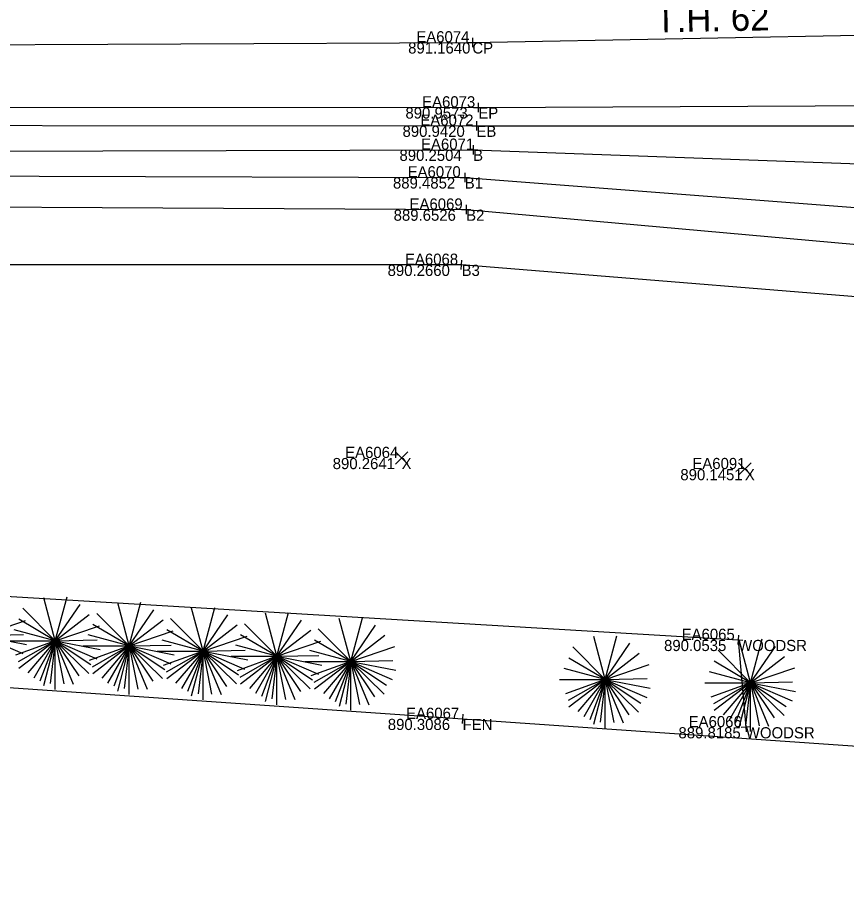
# Model space of a CAD drawing. Extents: x 179044 to 189691, y 286531 to 301257.
# Drawn here: x 180030.9 to 180120, y 300496.5 to 300591.3 of the extents above; entities that cross this region are included whole.
import ezdxf

# ---------------------------------------------------------------- set-up
doc = ezdxf.new("R2010")
doc.units = 0
for name, color, linetype in [('Default', 7, 'Continuous'), ('PV_X_COP', 7, 'Continuous'), ('PV_X_EOP', 7, 'Continuous'), ('PV_X_Shoulder_Aggregate', 7, 'Continuous'), ('RD_X_Fence', 7, 'Continuous'), ('SV_X_Break_Lines', 7, 'Continuous'), ('SV_X_Random_Point', 7, 'Continuous'), ('SV_X_Shot_Marker', 7, 'Continuous'), ('SV_X_Text_Comment', 7, 'Continuous'), ('SV_X_Text_Elevation', 7, 'Continuous'), ('SV_X_Text_Name', 7, 'Continuous'), ('VG_X_Cells', 7, 'Continuous'), ('VG_X_Text', 7, 'Continuous'), ('VG_X_Tree_Line_Lt', 7, 'Continuous')]:
    doc.layers.add(name, color=color, linetype=linetype)

msp = doc.modelspace()

# ---------------------------------------------------------------- linework, layer by layer
at = {"layer": 'PV_X_COP'}
msp.add_lwpolyline([(179370.611, 300584.893), (179476.831, 300585.936), (179562.951, 300586.92), (179659.852, 300587.603), (179771.173, 300587.773), (179881.154, 300588.595), (179985.728, 300588.166), (180079.826, 300588.612), (180147.691, 300589.874), (180172.034, 300590.636), (180187.456, 300591.905), (180203.618, 300593.325)], dxfattribs=at)
at = {"layer": 'PV_X_EOP'}
msp.add_lwpolyline([(179371.146, 300578.051), (179477.168, 300579.528), (179563.012, 300579.455), (179660.626, 300579.907), (179772.349, 300580.843), (179883.302, 300581.216), (179986.953, 300581.659), (180080.461, 300581.624), (180131.142, 300581.875), (180152.421, 300580.897), (180177.372, 300581.245), (180192.481, 300580.813), (180205.116, 300578.916), (180211.895, 300576.366), (180217.061, 300570.924), (180226.256, 300546.032), (180252.64, 300475.662), (180284.891, 300388.784), (180312.046, 300315.753), (180341.998, 300235.308)], dxfattribs=at)
at = {"layer": 'PV_X_Shoulder_Aggregate'}
msp.add_lwpolyline([(179563.451, 300578.229), (179660.977, 300578.016), (179772.748, 300578.901), (179883.7, 300579.446), (179986.895, 300579.719), (180080.262, 300579.655), (180131.517, 300579.632), (180152.892, 300578.404), (180177.169, 300578.87), (180192.854, 300577.824), (180203.732, 300575.396), (180212.869, 300569.272), (180224.05, 300544.426), (180250.422, 300474.503), (180282.665, 300386.992), (180309.922, 300313.986), (180339.844, 300234.334)], dxfattribs=at)
at = {"layer": 'RD_X_Fence'}
msp.add_lwpolyline([(179565.425, 300550.823), (179667.832, 300544.252), (179812.225, 300533.926), (179896.206, 300528.356), (179941.193, 300525.399), (180078.773, 300515.902), (180168.337, 300509.719), (180196.88, 300447.723), (180266.667, 300296.146), (180285.875, 300252.935)], dxfattribs=at)
at = {"layer": 'SV_X_Break_Lines'}
for points in [[(179565.115, 300573.15), (179662.025, 300574.398), (179773.068, 300575.457), (179882.867, 300576.482), (179986.954, 300576.827), (180079.906, 300577.073), (180132.276, 300575.162), (180173.558, 300573.472), (180187.352, 300573.774), (180198.853, 300570.766)], [(179565.766, 300571.109), (179663.199, 300570.888), (179773.087, 300572.831), (179882.326, 300573.106), (179987.447, 300574.391), (180079.006, 300574.101), (180132.144, 300569.99), (180164.614, 300565.351), (180185.409, 300564.026)], [(179565.763, 300567.872), (179663.335, 300568.017), (179772.883, 300569.466), (179881.609, 300569.697), (179987.857, 300571.139), (180079.155, 300570.638), (180132.418, 300565.887), (180165.824, 300561.088), (180185.221, 300560.101)], [(180320.902, 300212.184), (180282.069, 300307.438), (180254.033, 300376.286), (180214.216, 300457.225), (180192.833, 300518.475), (180187.002, 300524.649), (180178.544, 300551.918), (180167.492, 300556.189), (180133.433, 300560.27), (180078.668, 300564.705), (179988.563, 300564.714), (179881.16, 300565.14), (179774.574, 300564.41), (179665.201, 300563.792), (179565.532, 300563.693)]]:
    msp.add_lwpolyline(points, dxfattribs=at)
at = {"layer": 'SV_X_Random_Point'}
for p, q in [((180071.547, 300543.274), (180072.88, 300544.609)), ((180071.547, 300544.609), (180072.88, 300543.274)), ((180108.449, 300542.079), (180109.782, 300543.414)), ((180108.449, 300543.414), (180109.782, 300542.079))]:
    msp.add_line(p, q, dxfattribs=at)
at = {"layer": 'SV_X_Shot_Marker'}
for p, q in [((180079.824, 300589.112), (180079.829, 300588.112)), ((180079.326, 300588.61), (180080.326, 300588.615)), ((180079.826, 300588.612), (180079.826, 300588.612)), ((180079.961, 300581.624), (180080.961, 300581.624)), ((180080.461, 300582.124), (180080.461, 300581.124)), ((180080.461, 300581.624), (180080.461, 300581.624)), ((180079.762, 300579.655), (180080.762, 300579.654)), ((180080.262, 300580.155), (180080.262, 300579.155)), ((180080.262, 300579.655), (180080.262, 300579.655)), ((180079.905, 300577.573), (180079.907, 300576.573)), ((180079.406, 300577.072), (180080.406, 300577.074)), ((180079.906, 300577.073), (180079.906, 300577.073)), ((180079.008, 300574.601), (180079.005, 300573.602)), ((180078.506, 300574.103), (180079.506, 300574.1)), ((180079.006, 300574.101), (180079.006, 300574.101)), ((180079.158, 300571.138), (180079.152, 300570.138)), ((180078.655, 300570.641), (180079.655, 300570.635)), ((180079.155, 300570.638), (180079.155, 300570.638)), ((180078.627, 300564.207), (180078.708, 300565.204)), ((180079.166, 300564.665), (180078.169, 300564.746)), ((180078.668, 300564.705), (180078.668, 300564.705)), ((180107.899, 300524.417), (180108.897, 300524.358)), ((180108.428, 300524.887), (180108.368, 300523.888)), ((180108.398, 300524.388), (180108.398, 300524.388)), ((180078.275, 300515.936), (180079.272, 300515.867)), ((180078.808, 300516.401), (180078.739, 300515.403)), ((180078.773, 300515.902), (180078.773, 300515.902)), ((180109.727, 300515.049), (180108.731, 300514.96)), ((180109.185, 300515.502), (180109.273, 300514.506)), ((180109.229, 300515.004), (180109.229, 300515.004))]:
    msp.add_line(p, q, dxfattribs=at)
at = {"layer": 'VG_X_Cells'}
for p, q in [((180034.987, 300524.303), (180033.752, 300528.916)), ((180034.987, 300524.303), (180036.243, 300529.001)), ((180034.987, 300524.303), (180037.642, 300528.188)), ((180042.928, 300523.746), (180041.693, 300528.36)), ((180042.928, 300523.746), (180044.185, 300528.445)), ((180034.987, 300524.303), (180031.497, 300527.789)), ((180042.928, 300523.746), (180039.438, 300527.233)), ((180042.928, 300523.746), (180045.583, 300527.631)), ((180050.87, 300523.19), (180049.635, 300527.803)), ((180050.87, 300523.19), (180052.127, 300527.888)), ((180058.811, 300522.633), (180057.576, 300527.247)), ((180058.811, 300522.633), (180060.068, 300527.332)), ((180027.045, 300524.859), (180031.782, 300526.466)), ((180034.987, 300524.303), (180031.08, 300526.599)), ((180034.987, 300524.303), (180038.643, 300527.108)), ((180042.928, 300523.746), (180046.585, 300526.551)), ((180050.87, 300523.19), (180047.38, 300526.676)), ((180050.87, 300523.19), (180053.525, 300527.075)), ((180058.811, 300522.633), (180061.466, 300526.518)), ((180066.753, 300522.077), (180065.518, 300526.69)), ((180066.753, 300522.077), (180068.01, 300526.775)), ((180034.987, 300524.303), (180030.573, 300525.486)), ((180034.987, 300524.303), (180039.723, 300525.909)), ((180042.928, 300523.746), (180039.022, 300526.043)), ((180042.928, 300523.746), (180047.665, 300525.353)), ((180050.87, 300523.19), (180046.963, 300525.486)), ((180050.87, 300523.19), (180054.527, 300525.995)), ((180058.811, 300522.633), (180055.321, 300526.12)), ((180058.811, 300522.633), (180062.468, 300525.438)), ((180066.753, 300522.077), (180063.263, 300525.564)), ((180066.753, 300522.077), (180069.408, 300525.962)), ((180027.045, 300524.859), (180031.555, 300524.951)), ((180027.045, 300524.859), (180031.51, 300522.918)), ((180027.045, 300524.859), (180031.874, 300523.901)), ((180034.987, 300524.303), (180039.497, 300524.394)), ((180042.928, 300523.746), (180038.515, 300524.93)), ((180050.87, 300523.19), (180046.457, 300524.373)), ((180050.87, 300523.19), (180055.607, 300524.796)), ((180058.811, 300522.633), (180054.905, 300524.93)), ((180066.753, 300522.077), (180062.846, 300524.374)), ((180066.753, 300522.077), (180070.41, 300524.882)), ((180094.111, 300520.144), (180092.876, 300524.757)), ((180094.111, 300520.144), (180095.367, 300524.842)), ((180109.742, 300519.789), (180108.506, 300524.402)), ((180109.742, 300519.789), (180110.998, 300524.487)), ((180030.052, 300524.303), (180034.987, 300524.303)), ((180034.987, 300524.303), (180030.697, 300522.741)), ((180034.987, 300524.303), (180031.003, 300522.021)), ((180034.987, 300524.303), (180031.08, 300521.308)), ((180034.987, 300524.303), (180032.042, 300520.836)), ((180034.987, 300524.303), (180032.668, 300520.288)), ((180034.987, 300524.303), (180033.322, 300519.963)), ((180034.987, 300524.303), (180033.723, 300519.446)), ((180034.987, 300524.303), (180034.445, 300519.711)), ((180034.987, 300519.063), (180034.987, 300524.303)), ((180034.987, 300524.303), (180035.908, 300519.666)), ((180034.987, 300524.303), (180036.92, 300519.634)), ((180034.987, 300524.303), (180037.523, 300520.509)), ((180034.987, 300524.303), (180038.575, 300520.781)), ((180034.987, 300524.303), (180038.808, 300521.748)), ((180034.987, 300524.303), (180039.452, 300522.361)), ((180034.987, 300524.303), (180039.815, 300523.344)), ((180037.993, 300523.746), (180042.928, 300523.746)), ((180042.928, 300523.746), (180038.638, 300522.185)), ((180042.928, 300523.746), (180038.945, 300521.465)), ((180042.928, 300523.746), (180039.022, 300520.751)), ((180042.928, 300523.746), (180039.983, 300520.28)), ((180042.928, 300523.746), (180040.61, 300519.731)), ((180042.928, 300523.746), (180041.263, 300519.406)), ((180042.928, 300523.746), (180041.665, 300518.89)), ((180042.928, 300523.746), (180042.387, 300519.155)), ((180042.928, 300523.746), (180047.438, 300523.838)), ((180042.928, 300518.506), (180042.928, 300523.746)), ((180042.928, 300523.746), (180043.85, 300519.11)), ((180042.928, 300523.746), (180044.862, 300519.078)), ((180042.928, 300523.746), (180045.465, 300519.953)), ((180042.928, 300523.746), (180046.517, 300520.225)), ((180042.928, 300523.746), (180046.75, 300521.191)), ((180042.928, 300523.746), (180047.393, 300521.805)), ((180042.928, 300523.746), (180047.757, 300522.788)), ((180058.811, 300522.633), (180054.398, 300523.817)), ((180058.811, 300522.633), (180063.548, 300524.24)), ((180066.753, 300522.077), (180071.49, 300523.684)), ((180094.111, 300520.144), (180090.621, 300523.63)), ((180094.111, 300520.144), (180096.766, 300524.029)), ((180109.742, 300519.789), (180112.397, 300523.674)), ((180045.935, 300523.19), (180050.87, 300523.19)), ((180050.87, 300523.19), (180046.58, 300521.628)), ((180050.87, 300523.19), (180046.887, 300520.908)), ((180050.87, 300523.19), (180046.963, 300520.195)), ((180050.87, 300523.19), (180047.925, 300519.723)), ((180050.87, 300523.19), (180048.552, 300519.175)), ((180050.87, 300523.19), (180049.205, 300518.85)), ((180050.87, 300523.19), (180049.607, 300518.333)), ((180050.87, 300523.19), (180050.328, 300518.598)), ((180050.87, 300523.19), (180055.38, 300523.281)), ((180050.87, 300517.95), (180050.87, 300523.19)), ((180050.87, 300523.19), (180051.792, 300518.553)), ((180050.87, 300523.19), (180052.803, 300518.521)), ((180050.87, 300523.19), (180053.407, 300519.396)), ((180050.87, 300523.19), (180054.458, 300519.668)), ((180050.87, 300523.19), (180054.692, 300520.635)), ((180050.87, 300523.19), (180055.335, 300521.248)), ((180050.87, 300523.19), (180055.698, 300522.231)), ((180053.876, 300522.633), (180058.811, 300522.633)), ((180058.811, 300522.633), (180054.521, 300521.072)), ((180058.811, 300522.633), (180054.828, 300520.352)), ((180058.811, 300522.633), (180054.905, 300519.638)), ((180058.811, 300522.633), (180055.866, 300519.167)), ((180058.811, 300522.633), (180056.493, 300518.618)), ((180058.811, 300522.633), (180057.146, 300518.293)), ((180058.811, 300522.633), (180057.548, 300517.777)), ((180058.811, 300522.633), (180058.27, 300518.042)), ((180058.811, 300522.633), (180063.321, 300522.725)), ((180058.811, 300517.393), (180058.811, 300522.633)), ((180058.811, 300522.633), (180059.733, 300517.997)), ((180058.811, 300522.633), (180060.745, 300517.965)), ((180058.811, 300522.633), (180061.348, 300518.84)), ((180058.811, 300522.633), (180062.4, 300519.112)), ((180058.811, 300522.633), (180062.633, 300520.078)), ((180058.811, 300522.633), (180063.276, 300520.692)), ((180058.811, 300522.633), (180063.64, 300521.675)), ((180066.753, 300522.077), (180062.34, 300523.26)), ((180094.111, 300520.144), (180097.767, 300522.949)), ((180109.742, 300519.789), (180106.251, 300523.275)), ((180109.742, 300519.789), (180113.398, 300522.594)), ((180061.818, 300522.077), (180066.753, 300522.077)), ((180066.753, 300522.077), (180062.463, 300520.515)), ((180066.753, 300522.077), (180062.77, 300519.795)), ((180066.753, 300522.077), (180062.846, 300519.082)), ((180066.753, 300522.077), (180063.808, 300518.61)), ((180066.753, 300522.077), (180064.435, 300518.062)), ((180066.753, 300522.077), (180065.088, 300517.737)), ((180066.753, 300522.077), (180065.49, 300517.22)), ((180066.753, 300522.077), (180066.211, 300517.485)), ((180066.753, 300522.077), (180071.263, 300522.169)), ((180066.753, 300516.837), (180066.753, 300522.077)), ((180066.753, 300522.077), (180067.675, 300517.44)), ((180066.753, 300522.077), (180068.686, 300517.409)), ((180066.753, 300522.077), (180069.29, 300518.284)), ((180066.753, 300522.077), (180070.341, 300518.555)), ((180066.753, 300522.077), (180070.575, 300519.522)), ((180066.753, 300522.077), (180071.218, 300520.135)), ((180066.753, 300522.077), (180071.581, 300521.119)), ((180094.111, 300520.144), (180090.204, 300522.44)), ((180094.111, 300520.144), (180098.847, 300521.75)), ((180109.742, 300519.789), (180105.835, 300522.085)), ((180094.111, 300520.144), (180089.697, 300521.327)), ((180109.742, 300519.789), (180105.328, 300520.972)), ((180109.742, 300519.789), (180114.478, 300521.395)), ((180089.176, 300520.144), (180094.111, 300520.144)), ((180094.111, 300520.144), (180089.821, 300518.582)), ((180094.111, 300520.144), (180090.127, 300517.862)), ((180094.111, 300520.144), (180090.204, 300517.149)), ((180094.111, 300520.144), (180091.166, 300516.677)), ((180094.111, 300520.144), (180091.792, 300516.129)), ((180094.111, 300520.144), (180092.446, 300515.804)), ((180094.111, 300520.144), (180092.847, 300515.287)), ((180094.111, 300520.144), (180093.569, 300515.552)), ((180094.111, 300520.144), (180098.621, 300520.235)), ((180094.111, 300514.904), (180094.111, 300520.144)), ((180094.111, 300520.144), (180095.032, 300515.507)), ((180094.111, 300520.144), (180096.044, 300515.475)), ((180094.111, 300520.144), (180096.647, 300516.35)), ((180094.111, 300520.144), (180097.699, 300516.622)), ((180094.111, 300520.144), (180097.932, 300517.589)), ((180094.111, 300520.144), (180098.576, 300518.202)), ((180094.111, 300520.144), (180098.939, 300519.185)), ((180104.807, 300519.789), (180109.742, 300519.789)), ((180109.742, 300519.789), (180105.451, 300518.227)), ((180109.742, 300519.789), (180105.758, 300517.507)), ((180109.742, 300519.789), (180105.835, 300516.794)), ((180109.742, 300519.789), (180106.796, 300516.322)), ((180109.742, 300519.789), (180107.423, 300515.774)), ((180109.742, 300519.789), (180108.076, 300515.449)), ((180109.742, 300519.789), (180108.478, 300514.932)), ((180109.742, 300519.789), (180109.2, 300515.197)), ((180109.742, 300519.789), (180114.251, 300519.88)), ((180109.742, 300514.549), (180109.742, 300519.789)), ((180109.742, 300519.789), (180110.663, 300515.152)), ((180109.742, 300519.789), (180111.675, 300515.12)), ((180109.742, 300519.789), (180112.278, 300515.995)), ((180109.742, 300519.789), (180113.33, 300516.267)), ((180109.742, 300519.789), (180113.563, 300517.234)), ((180109.742, 300519.789), (180114.207, 300517.847)), ((180109.742, 300519.789), (180114.57, 300518.83))]:
    msp.add_line(p, q, dxfattribs=at)
at = {"layer": 'VG_X_Tree_Line_Lt'}
msp.add_lwpolyline([(179569.069, 300551.827), (179569.572, 300561.616), (179669.01, 300553.205), (179812.545, 300543.336), (179895.927, 300538.89), (179941.238, 300534.37), (180108.398, 300524.388), (180109.229, 300515.004)], dxfattribs=at)

# ---------------------------------------------------------------- texts
at = {"layer": 'Default'}
msp.add_text('T.H. 62', height=2.8, rotation=1.06539, dxfattribs=at).set_placement((180099.516, 300589.678))
at = {"layer": 'SV_X_Text_Comment'}
for s, height, p in [('CP', 1.2, (180079.826, 300587.412)), ('EP', 1.2, (180080.461, 300580.424)), ('EB', 1.2, (180080.262, 300578.455)), ('B', 1.2, (180079.906, 300575.873)), ('B1', 1.2, (180079.006, 300572.901)), ('B2', 1.2, (180079.155, 300569.438)), ('B3', 1.2, (180078.668, 300563.505)), ('X', 1.2, (180072.213, 300542.741)), ('X', 1.2, (180109.115, 300541.547)), ('WOODSR', 1.2, (180108.398, 300523.188)), ('TE', 0.12, (180034.987, 300524.183)), ('TE', 0.12, (180042.928, 300523.626)), ('TE', 0.12, (180050.87, 300523.07)), ('TE', 0.12, (180058.811, 300522.513)), ('TE', 0.12, (180066.753, 300521.957)), ('TE', 0.12, (180094.111, 300520.024)), ('TE', 0.12, (180109.742, 300519.669)), ('FEN', 1.2, (180078.773, 300514.702)), ('WOODSR', 1.2, (180109.229, 300513.804))]:
    msp.add_text(s, height=height, dxfattribs=at).set_placement(p)
at = {"layer": 'SV_X_Text_Elevation'}
for s, height, p in [('891.1640', 1.2, (180072.921, 300587.412)), ('890.9573', 1.2, (180072.628, 300580.424)), ('890.9420', 1.2, (180072.316, 300578.455)), ('890.2504', 1.2, (180071.988, 300575.873)), ('889.4852', 1.2, (180071.287, 300572.901)), ('889.6526', 1.2, (180071.36, 300569.438)), ('890.2660', 1.2, (180070.712, 300563.505)), ('890.2641', 1.2, (180064.809, 300542.741)), ('890.1451', 1.2, (180102.184, 300541.547)), ('890.0535', 1.2, (180100.433, 300523.188)), ('889.9400', 0.06, (180093.712, 300520.084)), ('889.9930', 0.06, (180109.348, 300519.729)), ('890.3086', 1.2, (180070.733, 300514.702)), ('889.8185', 1.2, (180101.983, 300513.804))]:
    msp.add_text(s, height=height, dxfattribs=at).set_placement(p)
at = {"layer": 'SV_X_Text_Name'}
for s, height, p in [('EA6074', 1.2, (180073.798, 300588.612)), ('EA6073', 1.2, (180074.424, 300581.624)), ('EA6072', 1.2, (180074.234, 300579.655)), ('EA6071', 1.2, (180074.306, 300577.073)), ('EA6070', 1.2, (180072.865, 300574.101)), ('EA6069', 1.2, (180073.07, 300570.638)), ('EA6068', 1.2, (180072.583, 300564.705)), ('EA6064', 1.2, (180066.148, 300543.941)), ('EA6091', 1.2, (180103.478, 300542.747)), ('EA6065', 1.2, (180102.323, 300524.388)), ('SV5027', 0.06, (180093.808, 300520.144)), ('SV5028', 0.06, (180109.439, 300519.789)), ('EA6067', 1.2, (180072.698, 300515.902)), ('EA6066', 1.2, (180103.079, 300515.004))]:
    msp.add_text(s, height=height, dxfattribs=at).set_placement(p)
at = {"layer": 'VG_X_Text'}
for p in [(180034.987, 300524.303), (180042.928, 300523.746), (180050.87, 300523.19), (180058.811, 300522.633), (180066.753, 300522.077), (180094.111, 300520.144), (180109.742, 300519.789)]:
    msp.add_text(' NOTE:8', height=0.12, dxfattribs=at).set_placement(p)

doc.saveas('drawing.dxf')
